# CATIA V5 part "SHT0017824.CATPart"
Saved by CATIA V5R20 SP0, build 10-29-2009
Part number: SHT0017824-20241219
Source: Unknown
Bounding box of the stored display mesh (mm): x -544.085 to 25.758, y -866.5 to -591.5, z 0.9 to 106.4
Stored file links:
  F:\福田A6\1-数据\6-冻结数据\第九批\设变\宽车底部支架设变ECR0011068-20241213\SHT0016014-宽车主驾驶底部支架焊接总成\更改后数据-SHT0017824\SHT0016014-宽车主驾驶底部支架焊接总成\SHT0017824.CATPart
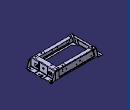
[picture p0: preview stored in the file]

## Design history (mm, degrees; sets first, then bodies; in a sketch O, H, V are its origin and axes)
Set1
  Point1 to Point4: stored without definition
Body1 "几何体" (main body)
Body2 "SHT0016151-支撑轴套"
  Solid1: solid without history
Body3 "SHT0016151-支撑轴套"
  Solid2: solid without history
Body4 "SHT0016014.1\\SHT0016145-宽车主驾驶前侧钣金"
  Solid3: solid without history
Body5 "SHT0016014.1\\SHT0016148-宽车主驾驶左侧钣金"
  Solid4: solid without history
Body6 "SHT0016014.1\\SHT0016148-宽车主驾驶左侧钣金"
  Solid5: solid without history
Body7 "SHT0016151-支撑轴套"
  Solid6: solid without history
Body8 "SHT0016014.1\\Q37108-焊接方螺母"
  Solid7: solid without history
Body9 "SHT0016014.1\\Q37108-焊接方螺母"
  Solid8: solid without history
Body10 "SHT0016014.1\\Q37108-焊接方螺母"
  Solid9: solid without history
Body11 "SHT0016014.1\\Q37108-焊接方螺母"
  Solid10: solid without history
Body12 "SHT0016014.1\\Q37108-焊接方螺母"
  Solid11: solid without history
Body13 "SHT0016014.1\\Q37108-焊接方螺母"
  Solid12: solid without history
Body14 "SHT0016014.1\\SHT0016146-宽车主驾驶后侧钣金"
  Solid13: solid without history
Body15 "Q37108-焊接方螺母"
  Solid14: solid without history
